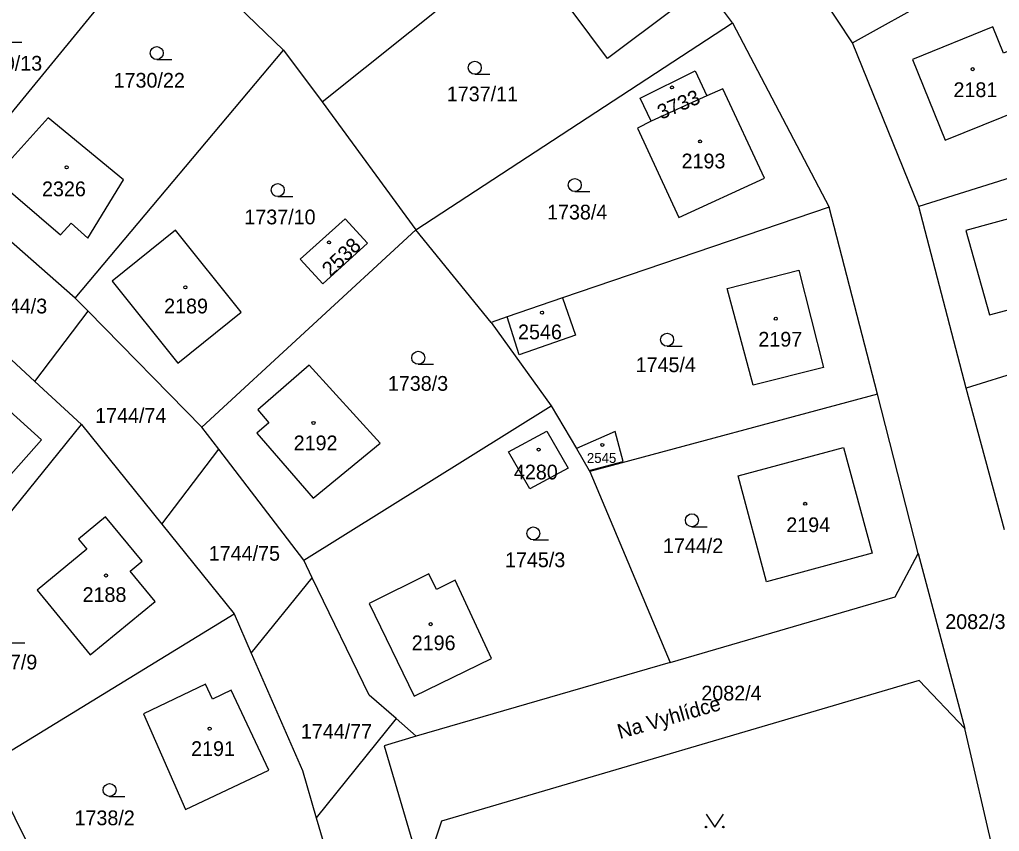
# Model space of a CAD drawing. Extents: x -679220 to -673243, y -1075091 to -1066557.
# Drawn here: x -676748.4 to -676635.3, y -1072173.6 to -1072080 of the extents above; entities that cross this region are included whole.
import ezdxf

# ---------------------------------------------------------------- set-up
doc = ezdxf.new("R2010")
doc.units = 0
for name, color, linetype in [('Hranice parcel', 7, 'Continuous'), ('Parcelní čísla', 7, 'Continuous'), ('Pop  PČ popisy', 7, 'Continuous'), ('Značky budov', 7, 'Continuous'), ('Značky kultur', 7, 'Continuous')]:
    doc.layers.add(name, color=color, linetype=linetype)

msp = doc.modelspace()

# ---------------------------------------------------------------- linework, layer by layer
at = {"layer": 'Hranice parcel'}
for p, q in [((-676713.44, -1072089.47), (-676679.46, -1072062.24)), ((-676652.26, -1072082.65), (-676625.25, -1072067.62)), ((-676652.26, -1072082.65), (-676662.02, -1072067.93)), ((-676756.41, -1072099.41), (-676731.81, -1072069.41)), ((-676666.13, -1072080.35), (-676674.27, -1072069.3)), ((-676726.67, -1072075.04), (-676717.9, -1072083.5)), ((-676702.64, -1072104.22), (-676666.13, -1072080.35)), ((-676666.13, -1072080.35), (-676654.96, -1072101.6)), ((-676741.94, -1072112.1), (-676717.9, -1072083.5)), ((-676717.9, -1072083.5), (-676713.44, -1072089.47)), ((-676644.62, -1072101.51), (-676652.26, -1072082.65)), ((-676669.09, -1072088.76), (-676675.5, -1072091.7)), ((-676713.44, -1072089.47), (-676702.64, -1072104.22)), ((-676618.37, -1072093.31), (-676644.62, -1072101.51)), ((-676741.94, -1072112.1), (-676756.41, -1072099.41)), ((-676654.96, -1072101.6), (-676685.71, -1072112.07)), ((-676649.38, -1072123.18), (-676654.96, -1072101.6)), ((-676639.14, -1072122.45), (-676644.62, -1072101.51)), ((-676727.32, -1072126.96), (-676702.64, -1072104.22)), ((-676693.96, -1072114.88), (-676702.64, -1072104.22)), ((-676756.69, -1072112.4), (-676746.59, -1072121.71)), ((-676740.46, -1072113.6), (-676741.94, -1072112.1)), ((-676685.71, -1072112.07), (-676692.11, -1072114.25)), ((-676746.59, -1072121.71), (-676740.46, -1072113.6)), ((-676727.32, -1072126.96), (-676740.46, -1072113.6)), ((-676692.11, -1072114.25), (-676693.96, -1072114.88)), ((-676693.96, -1072114.88), (-676687.02, -1072124.5)), ((-676612.35, -1072114.16), (-676639.14, -1072122.45)), ((-676746.59, -1072121.71), (-676741.21, -1072126.67)), ((-676649.38, -1072123.18), (-676682.57, -1072132.06)), ((-676644.68, -1072141.52), (-676649.38, -1072123.18)), ((-676634.73, -1072138.81), (-676639.14, -1072122.45)), ((-676715.58, -1072142.29), (-676687.02, -1072124.5)), ((-676687.02, -1072124.5), (-676684.12, -1072129.43)), ((-676762.97, -1072153.46), (-676741.21, -1072126.67)), ((-676741.21, -1072126.67), (-676731.95, -1072138.15)), ((-676725.36, -1072129.52), (-676727.32, -1072126.96)), ((-676731.95, -1072138.15), (-676725.36, -1072129.52)), ((-676715.58, -1072142.29), (-676725.36, -1072129.52)), ((-676684.12, -1072129.43), (-676682.63, -1072131.97)), ((-676682.63, -1072131.97), (-676682.57, -1072132.06)), ((-676682.57, -1072132.06), (-676673.32, -1072154.08)), ((-676731.95, -1072138.15), (-676723.6, -1072148.5)), ((-676714.59, -1072144.32), (-676715.58, -1072142.29)), ((-676644.68, -1072141.52), (-676639.3, -1072161.72)), ((-676721.63, -1072153.02), (-676714.59, -1072144.32)), ((-676751.97, -1072165.85), (-676723.6, -1072148.5)), ((-676723.6, -1072148.5), (-676721.63, -1072153.02)), ((-676673.32, -1072154.08), (-676702.61, -1072162.59)), ((-676704.91, -1072160.57), (-676714.14, -1072172.01)), ((-676702.61, -1072162.59), (-676704.91, -1072160.57)), ((-676635.37, -1072178.74), (-676639.3, -1072161.72)), ((-676743.31, -1072183.24), (-676751.97, -1072165.85)), ((-676714.14, -1072172.01), (-676713.35, -1072174.73))]:
    msp.add_line(p, q, dxfattribs=at)
for points in [[(-676686.41, -1072072.98), (-676681.8, -1072069.7), (-676680.32, -1072071.69), (-676678.91, -1072070.64), (-676672.87, -1072078.75), (-676680.53, -1072084.45), (-676686.64, -1072076.24), (-676684.93, -1072074.97), (-676686.41, -1072072.98)], [(-676633.27, -1072083.18), (-676634.85, -1072083.83), (-676636.08, -1072080.81), (-676645.34, -1072084.58), (-676641.57, -1072093.86), (-676626.06, -1072087.6), (-676628.17, -1072082.38), (-676632.86, -1072084.2), (-676633.27, -1072083.18)], [(-676675.5, -1072091.7), (-676676.77, -1072089.02), (-676670.41, -1072085.9), (-676669.09, -1072088.76)], [(-676675.5, -1072091.7), (-676677.07, -1072092.49), (-676672.31, -1072102.79), (-676662.41, -1072098.26), (-676667.21, -1072087.97), (-676669.09, -1072088.76)], [(-676740.5, -1072105.16), (-676736.38, -1072098.43), (-676745.06, -1072091.31), (-676751.32, -1072098.22), (-676743.64, -1072104.78), (-676742.41, -1072103.46), (-676740.5, -1072105.16)], [(-676627.04, -1072108.94), (-676629.07, -1072101.52), (-676639.19, -1072104.29), (-676636.48, -1072114.02), (-676626.49, -1072111.38)], [(-676710.81, -1072102.94), (-676715.98, -1072107.6), (-676713.38, -1072110.43), (-676708.23, -1072105.76), (-676710.81, -1072102.94)], [(-676737.67, -1072110.12), (-676730.09, -1072119.58), (-676722.78, -1072113.72), (-676730.36, -1072104.26), (-676737.67, -1072110.12)], [(-676658.46, -1072108.87), (-676655.61, -1072120.08), (-676663.72, -1072122.14), (-676666.73, -1072110.97), (-676658.46, -1072108.87)], [(-676685.71, -1072112.07), (-676684.24, -1072116.37), (-676690.71, -1072118.61), (-676692.11, -1072114.25)], [(-676762.8, -1072129.36), (-676759.8, -1072132.05), (-676756.85, -1072128.71), (-676750.87, -1072134.07), (-676745.81, -1072128.41), (-676754.79, -1072120.35), (-676759.86, -1072125.98), (-676762.8, -1072129.36)], [(-676720.98, -1072127.67), (-676714.49, -1072135.15), (-676706.77, -1072128.81), (-676714.96, -1072119.83), (-676720.89, -1072124.97), (-676719.6, -1072126.47), (-676720.98, -1072127.67)], [(-676687.55, -1072127.41), (-676685.08, -1072131.69), (-676689.48, -1072134.09), (-676691.94, -1072129.82), (-676687.55, -1072127.41)], [(-676682.63, -1072131.97), (-676678.73, -1072130.92), (-676679.65, -1072127.47), (-676684.12, -1072129.43)], [(-676650.02, -1072141.5), (-676662.2, -1072144.79), (-676665.46, -1072132.56), (-676653.29, -1072129.32), (-676650.02, -1072141.5)], [(-676746.31, -1072145.76), (-676740.22, -1072153.21), (-676732.7, -1072147.07), (-676735.61, -1072143.57), (-676734.22, -1072142.42), (-676738.46, -1072137.3), (-676741.56, -1072139.87), (-676740.6, -1072141.03), (-676746.31, -1072145.76)], [(-676673.32, -1072154.08), (-676647.36, -1072146.54), (-676644.68, -1072141.52)], [(-676704.91, -1072160.57), (-676708.01, -1072157.86), (-676714.59, -1072144.32)], [(-676702.82, -1072157.98), (-676693.9, -1072153.62), (-676698.09, -1072144.6), (-676700.27, -1072145.68), (-676701.15, -1072143.89), (-676708.04, -1072147.3), (-676702.82, -1072157.98)], [(-676721.63, -1072153.02), (-676715.73, -1072166.56), (-676714.14, -1072172.01)], [(-676734.05, -1072160), (-676729.22, -1072171.04), (-676719.61, -1072166.5), (-676723.96, -1072157.3), (-676726.09, -1072158.31), (-676726.89, -1072156.61), (-676734.05, -1072160)], [(-676639.3, -1072161.72), (-676644.57, -1072156.18), (-676699.67, -1072172.4), (-676701.82, -1072178.86)], [(-676702.61, -1072162.59), (-676706.29, -1072163.7), (-676701.82, -1072178.86)]]:
    msp.add_lwpolyline(points, dxfattribs=at)
at = {"layer": 'Značky budov'}
for centre in [(-676638.4, -1072085.69), (-676673.1, -1072087.8), (-676669.85, -1072094.02), (-676742.93, -1072097), (-676712.66, -1072105.67), (-676729.23, -1072110.84), (-676688.09, -1072113.77), (-676661.12, -1072114.46), (-676714.45, -1072126.48), (-676681.13, -1072129.01), (-676688.48, -1072129.55), (-676657.73, -1072135.8), (-676738.39, -1072144.07), (-676700.93, -1072149.68), (-676726.43, -1072161.72)]:
    msp.add_circle(centre, 0.175, dxfattribs=at)
at = {"layer": 'Značky kultur'}
for p, q in [((-676749.85, -1072082.57), (-676748.1, -1072082.57)), ((-676732.54, -1072084.58), (-676730.79, -1072084.58)), ((-676695.84, -1072086.27), (-676694.09, -1072086.27)), ((-676718.58, -1072100.38), (-676716.83, -1072100.38)), ((-676684.31, -1072099.8), (-676682.56, -1072099.8)), ((-676673.66, -1072117.63), (-676671.91, -1072117.63)), ((-676702.36, -1072119.72), (-676700.61, -1072119.72)), ((-676670.8, -1072138.45), (-676669.05, -1072138.45)), ((-676689.09, -1072139.96), (-676687.34, -1072139.96)), ((-676749.52, -1072151.85), (-676747.77, -1072151.85)), ((-676737.97, -1072169.55), (-676736.22, -1072169.55))]:
    msp.add_line(p, q, dxfattribs=at)
msp.add_lwpolyline([(-676669.17, -1072171.57), (-676668.17, -1072173.07), (-676667.17, -1072171.57)], dxfattribs=at)
for centre, radius in [((-676732.54, -1072083.83), 0.75), ((-676695.84, -1072085.52), 0.75), ((-676684.31, -1072099.05), 0.75), ((-676718.58, -1072099.63), 0.75), ((-676673.66, -1072116.88), 0.75), ((-676702.36, -1072118.97), 0.75), ((-676670.8, -1072137.7), 0.75), ((-676689.09, -1072139.21), 0.75), ((-676737.97, -1072168.8), 0.75), ((-676669.17, -1072173.07), 0.1), ((-676667.17, -1072173.07), 0.1)]:
    msp.add_circle(centre, radius, dxfattribs=at)

# ---------------------------------------------------------------- texts
at = {"layer": 'Parcelní čísla'}
for s, height, p in [('1730/13', 1.7, (-676753.97, -1072085.86)), ('1730/22', 1.7, (-676737.51, -1072087.82)), ('1737/11', 1.7, (-676699.07, -1072089.39)), ('2181', 1.7, (-676640.62, -1072088.91)), ('2193', 1.7, (-676671.99, -1072097.13)), ('2326', 1.7, (-676745.77, -1072100.34)), ('1738/4', 1.7, (-676687.51, -1072103.02)), ('1737/10', 1.7, (-676722.43, -1072103.58)), ('1744/3', 1.7, (-676752.13, -1072113.85)), ('2189', 1.7, (-676731.68, -1072113.85)), ('2546', 1.7, (-676690.85, -1072116.83)), ('2197', 1.7, (-676663.13, -1072117.68)), ('1745/4', 1.7, (-676677.29, -1072120.62)), ('1738/3', 1.7, (-676705.87, -1072122.77)), ('1744/74', 1.7, (-676739.64, -1072126.47)), ('2192', 1.7, (-676716.74, -1072129.63)), ('2545', 1.14, (-676682.91, -1072131.09)), ('4280', 1.7, (-676691.33, -1072132.99)), ('2194', 1.7, (-676659.91, -1072139.07)), ('1744/2', 1.7, (-676674.14, -1072141.49)), ('1744/75', 1.7, (-676726.53, -1072142.36)), ('1745/3', 1.7, (-676692.36, -1072143.11)), ('2188', 1.7, (-676741.09, -1072147.12)), ('2082/3', 1.7, (-676641.57, -1072150.24)), ('2196', 1.7, (-676703.12, -1072152.68)), ('1737/9', 1.7, (-676753.27, -1072154.9)), ('2082/4', 1.7, (-676669.71, -1072158.48)), ('1744/77', 1.7, (-676715.91, -1072162.89)), ('2191', 1.7, (-676728.57, -1072164.88)), ('1738/2', 1.7, (-676742.02, -1072172.86))]:
    msp.add_text(s, height=height, dxfattribs=at).set_placement(p)
for s, rotation, p in [('3733', 23, (-676674.34, -1072091.53)), ('2538', 44, (-676712.48, -1072109.71))]:
    msp.add_text(s, height=1.7, rotation=rotation, dxfattribs=at).set_placement(p)
at = {"layer": 'Pop  PČ popisy'}
msp.add_text('Na Vyhlídce', height=1.7, rotation=16, dxfattribs=at).set_placement((-676679.11, -1072162.93))

doc.saveas('drawing.dxf')
